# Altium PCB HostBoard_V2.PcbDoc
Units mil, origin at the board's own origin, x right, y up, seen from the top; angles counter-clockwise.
Board outline 3920 x 3930 mil, 2 copper layers (Top Layer, Bottom Layer); 20 components, 27 nets, 144 pads, 88 vias.
Unrouted connection lines stored in the file: 1.
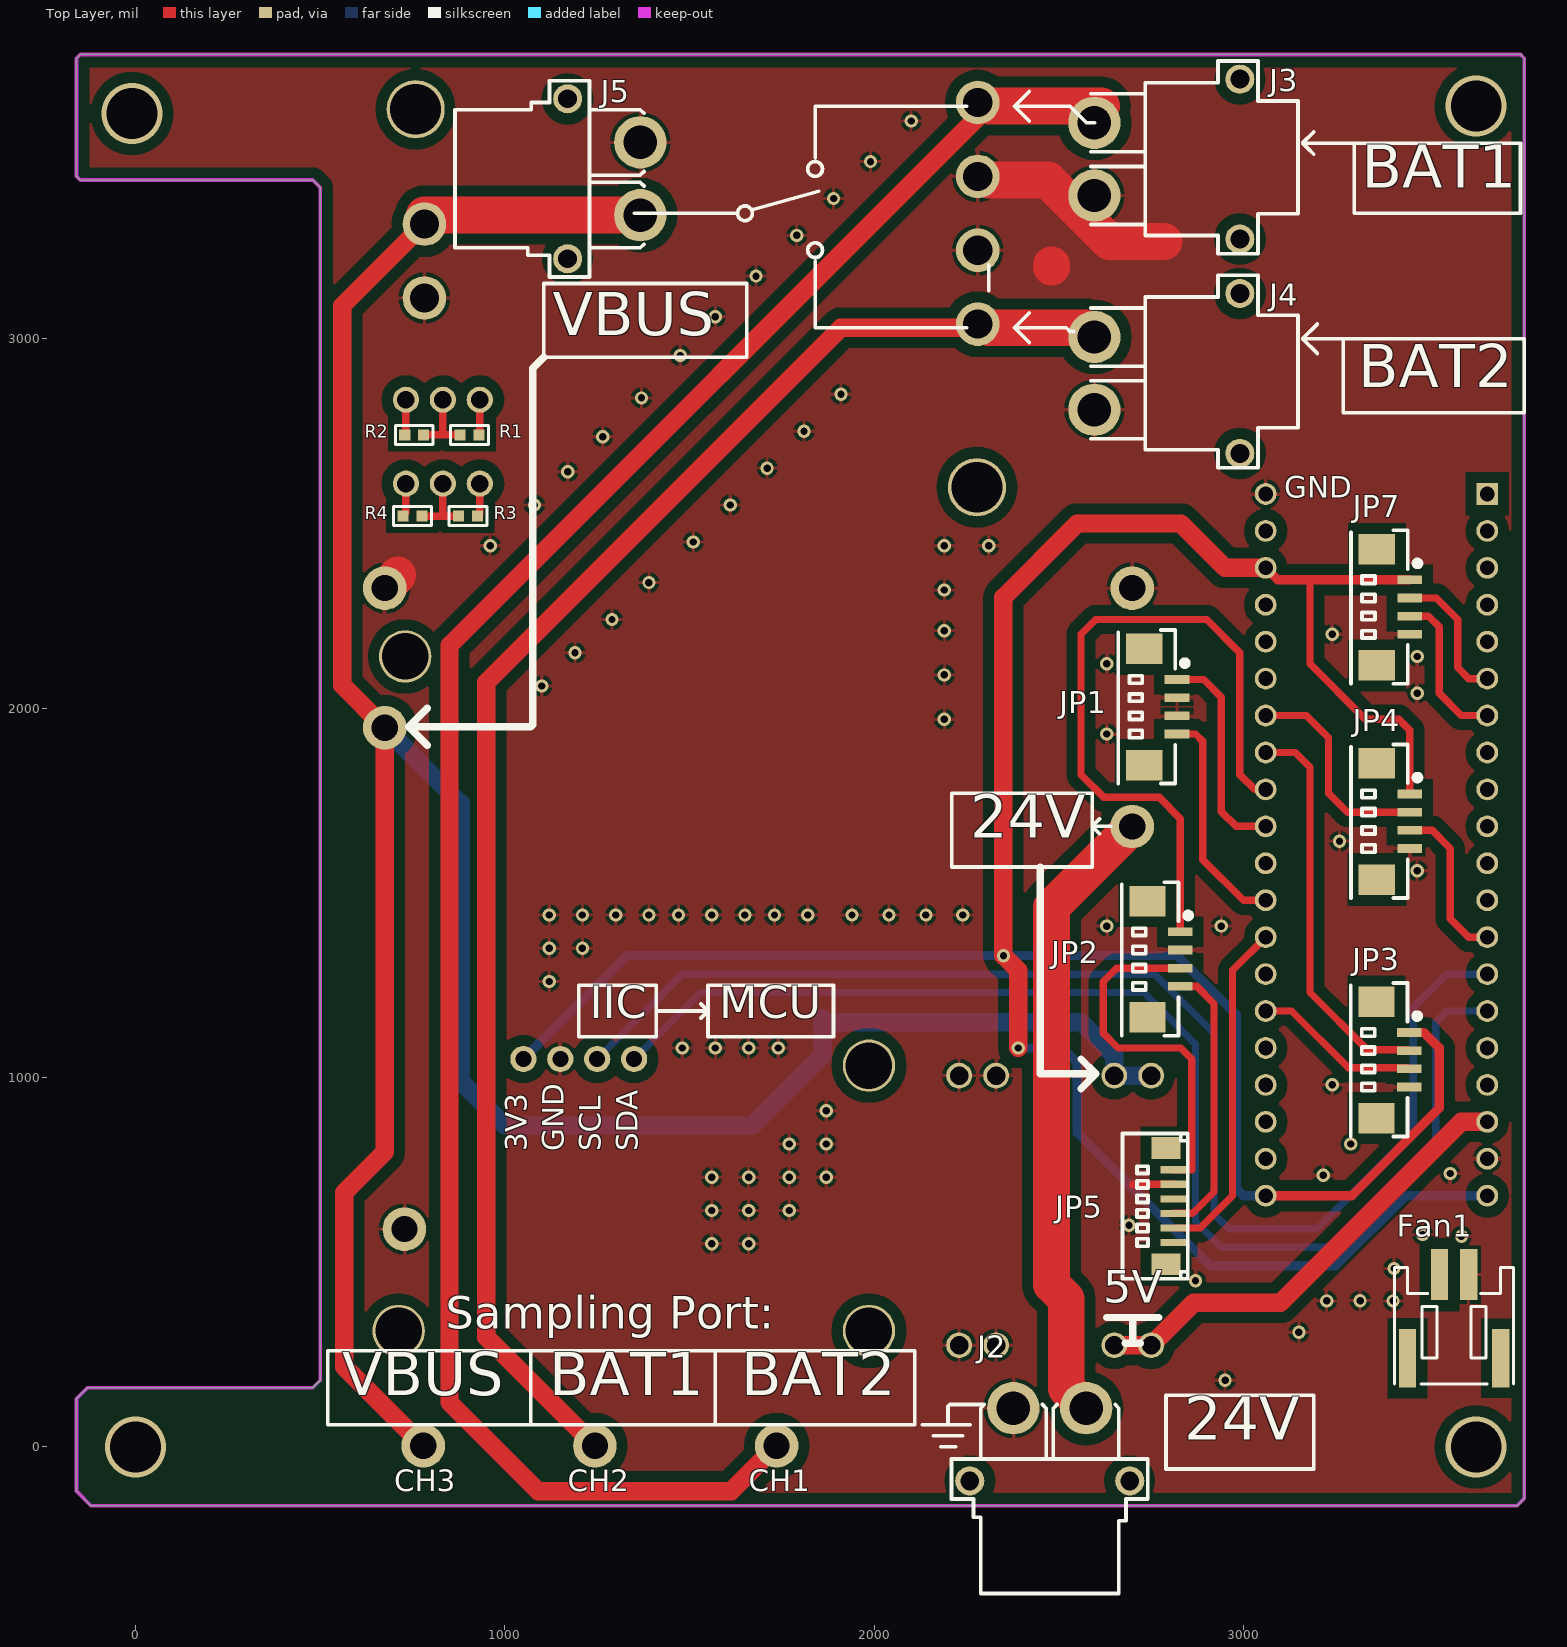
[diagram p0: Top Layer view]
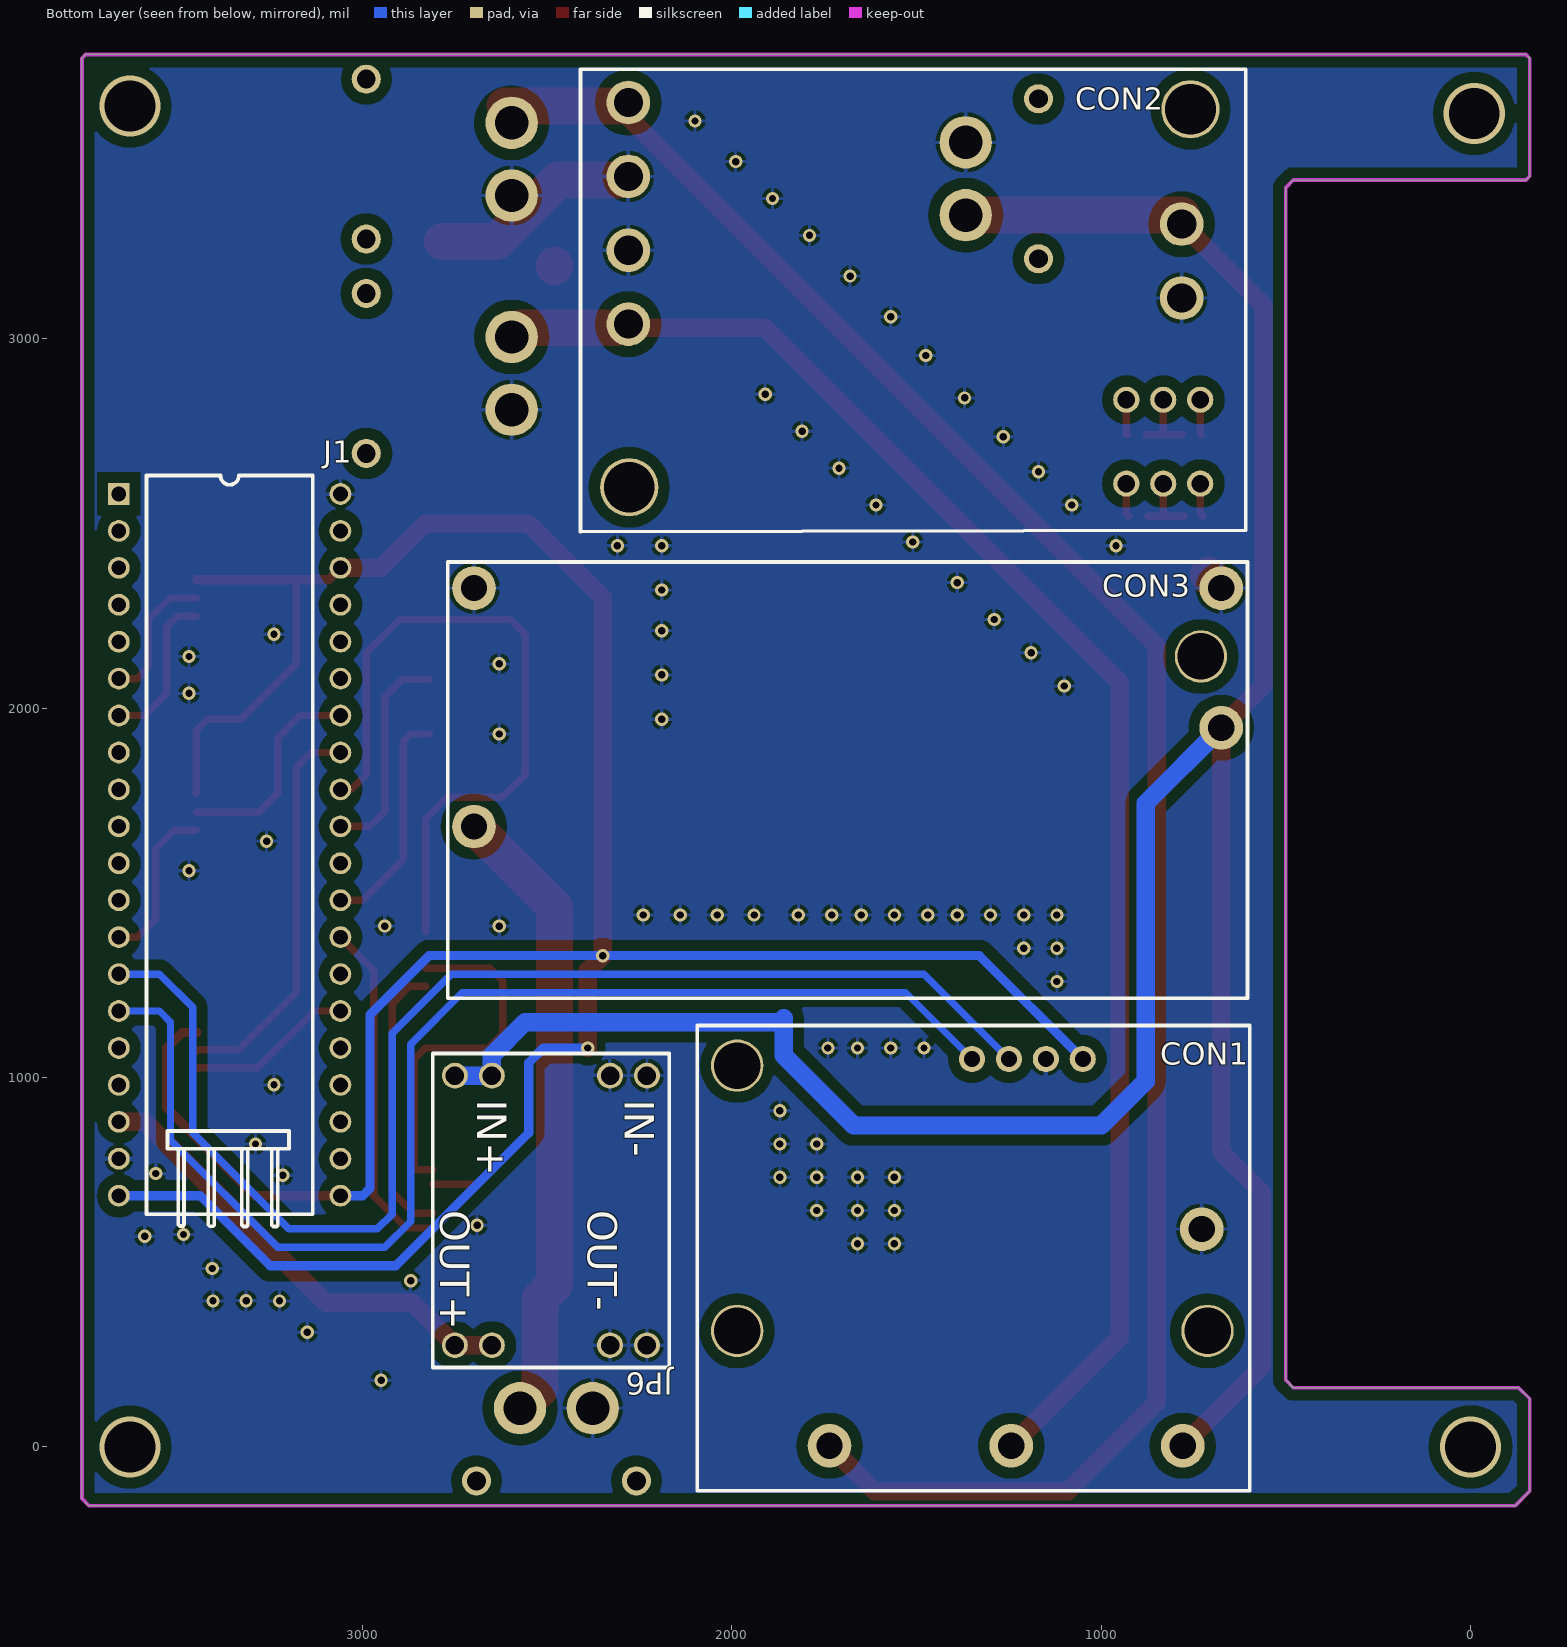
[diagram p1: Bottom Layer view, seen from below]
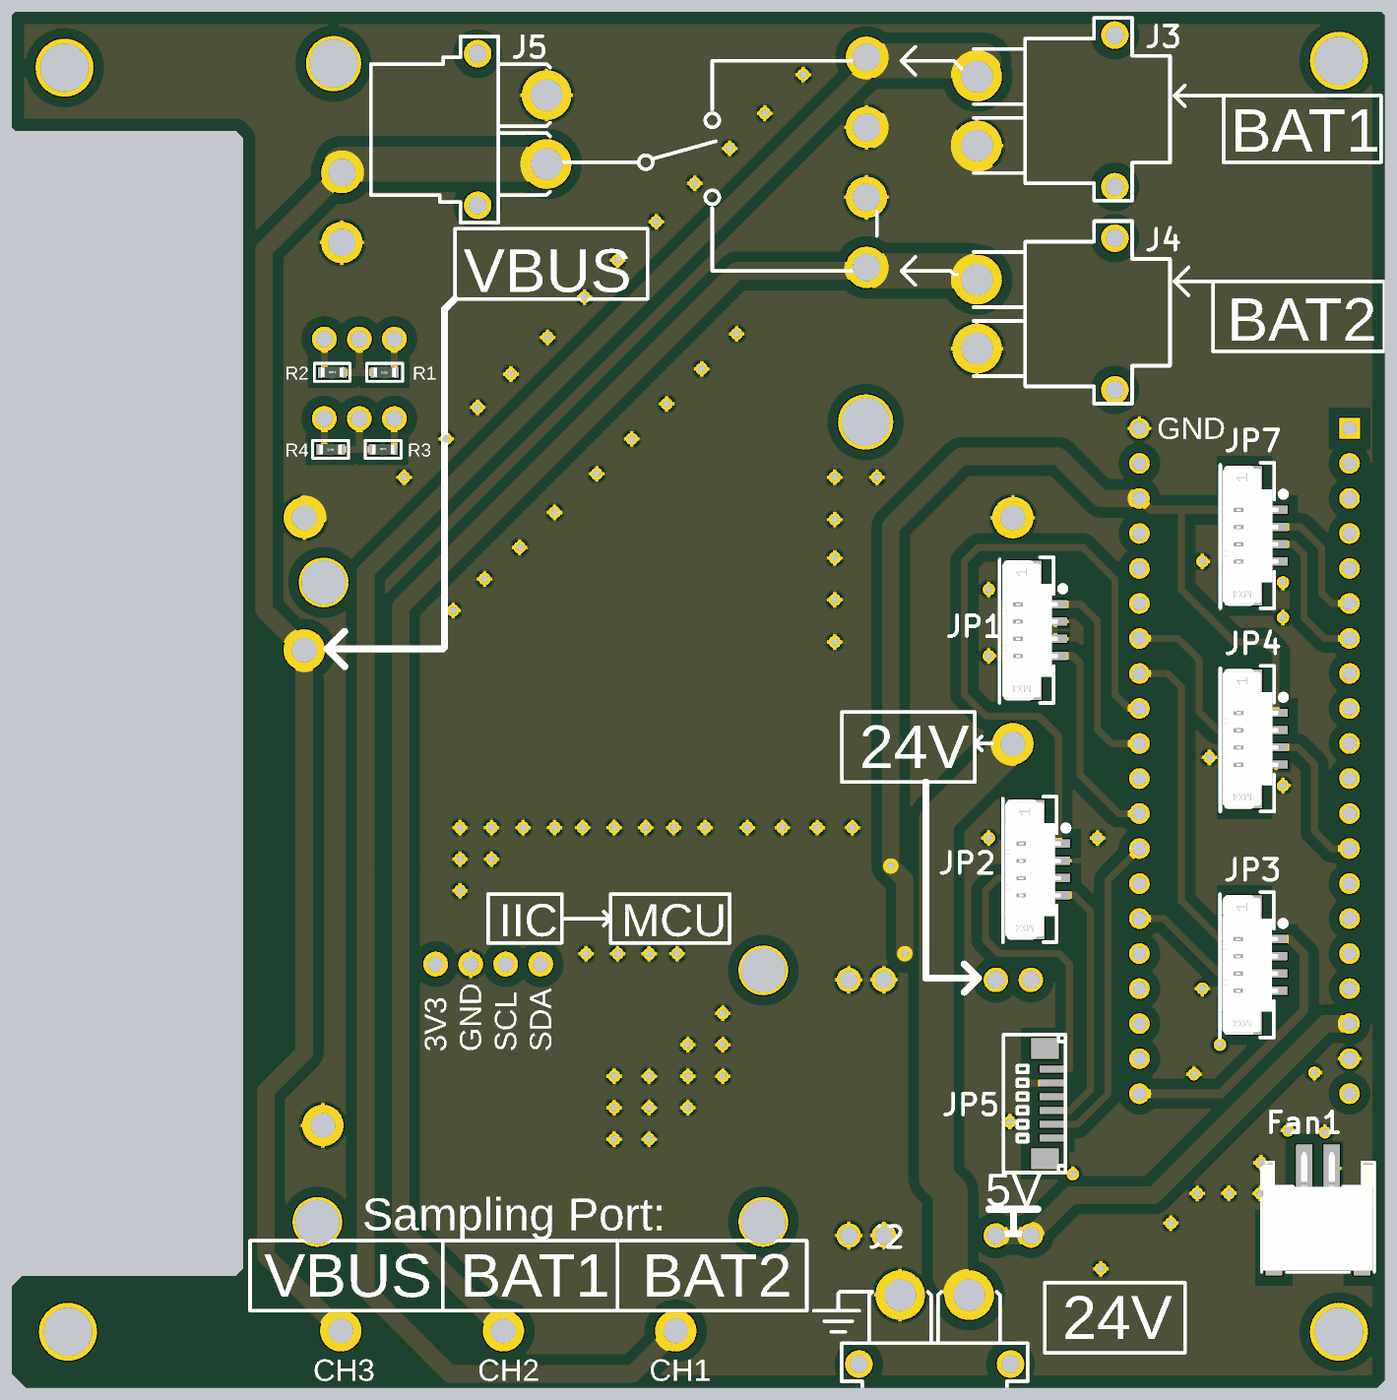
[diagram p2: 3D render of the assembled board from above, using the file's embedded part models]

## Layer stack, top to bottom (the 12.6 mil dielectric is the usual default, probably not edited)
Top Solder: solder mask 0.4, Solder Resist, Dk 3.5
Top Layer: signal copper 1.4
Dielectric 1: dielectric 12.6, FR-4, Dk 4.8
Bottom Layer: signal copper 1.4
Bottom Solder: solder mask 0.4, Solder Resist, Dk 3.5

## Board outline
-160,-120 -160,130 -130,160 480,160 500,180 500,3410 480,3430 -150,3430 -160,3440 -160,3760 -150,3770 3750,3770 3760,3760 3760,-140 3740,-160 -120,-160

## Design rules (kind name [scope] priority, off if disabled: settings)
Clearance [All] p1: gap=10 ignorepadtopadclearanceinfootprint=FALSE except(0: Arc-Hole Track-Hole SMDPad-Hole THPad-Hole Via-Hole Fill-Hole Poly-Hole Region-Hole Text-Hole; 30: Arc-Fill Arc-Poly Arc-Region Track-Fill Track-Poly Track-Region SMDPad-Fill SMDPad-Poly SMDPad-Region THPad-Fill THPad-Poly THPad-Region Via-Fill Via-Poly Via-Region Fill-Fill Fill-Poly Fill-Region Poly-Poly Poly-Region Region-Region)
PolygonConnect [All] p1: connectstyle=Relief reliefconductorwidth=10 reliefentries=4 polygonreliefangle="90 Angle" airgapwidth=10
RoutingVias [All] p1: holewidth=28 width=50 viastyle="Through Hole" minholewidth=28 minwidth=50 maxholewidth=28 maxwidth=50
SolderMaskExpansion [All] p1: expansion=4
Width [All] p1: maxlimit=196.85 minlimit=10 preferedwidth=39.37 minimp=50.000000 maximp=50.000000 favimp=50.000000
30 further rules are at their usual default settings.

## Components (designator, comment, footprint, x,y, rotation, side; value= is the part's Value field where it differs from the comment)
CON1 "Stereye-INA3221" STEREYE-INA3221 2094.09,-119.29 r90 bottom
CON2 "Stereye-PowerPath" STEREYE-POWERPATH 2410,3730 r180 bottom
CON3 "Stereye-BOOST" STEREYE-BOOST 1686.69,2002.2 r0 bottom
Fan1 "HDR-1X2" PH2.0-WS-2P 3570,240 r0 top
J1 "C8T6" C8T6 3360,1630 r180 bottom
J2 "CON2" "XT30 - F" 2475.29,104.71 r180 top
J3 "CON2" "XT30 - M" 2596.3,3486.54 r270 top
J4 "CON2" "XT30 - M" 2596.3,2906.54 r270 top
J5 "CON2" "XT30 - F" 1366.85,3433.46 r90 top
JP1 "KEY1" "MX 1.25-LS-4P" 2731,2003.28 r270 top
JP2 "KEY2" "MX 1.25-LS-4P" 2740,1320 r270 top
JP3 "HDR-1X4" "MX 1.25-LS-4P" 3360,1047.48 r270 top
JP4 "HDR-1X4" "MX 1.25-LS-4P" 3361,1693.28 r270 top
JP5 "HDR-1X6" SH1.0 2810,750 r270 top
JP6 "Stereye buck module" "STEREYE BUCK MODULE" 2490,640 r270 bottom
JP7 "HDR-1X4" "MX 1.25-LS-4P" 3361,2273.28 r270 top
R1 "68K" "R 0603_L" 904.41,2740 r180 top
R2 "30K" "R 0603_L" 754.41,2740 r0 top
R3 "68K" "R 0603_L" 900,2520 r0 top
R4 "36K" "R 0603_L" 750,2520 r180 top

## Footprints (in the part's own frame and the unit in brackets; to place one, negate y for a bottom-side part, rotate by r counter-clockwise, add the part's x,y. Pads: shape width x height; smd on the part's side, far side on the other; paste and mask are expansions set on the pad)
C8T6 [mm]
  rect 1.5x1.5 hole 1.016: 1(-7.62,24.13)
  round 1.5 hole 1.016: 2(-7.62,21.59) 3(-7.62,19.05) 4(-7.62,16.51) 5(-7.62,13.97) 6(-7.62,11.43) 7(-7.62,8.89) 8(-7.62,6.35) 9(-7.62,3.81) 10(-7.62,1.27) 11(-7.62,-1.27) 12(-7.62,-3.81) 13(-7.62,-6.35) 14(-7.62,-8.89) 15(-7.62,-11.43) 16(-7.62,-13.97) 17(-7.62,-16.51) 18(-7.62,-19.05) 19(-7.62,-21.59) 20(-7.62,-24.13) 21(7.62,-24.13) 22(7.62,-21.59) 23(7.62,-19.05) 24(7.62,-16.51) 25(7.62,-13.97) 26(7.62,-11.43) 27(7.62,-8.89) 28(7.62,-6.35) 29(7.62,-3.81) 30(7.62,-1.27) 31(7.62,1.27) 32(7.62,3.81) 33(7.62,6.35) 34(7.62,8.89) 35(7.62,11.43) 36(7.62,13.97) 37(7.62,16.51) 38(7.62,19.05) 39(7.62,21.59) 40(7.62,24.13)
  silkscreen extent -5.72,-26.25 5.72,25.4
"MX 1.25-LS-4P" [mm] "长：9.75m，宽：3.7mm，高：4.7mm"
  rect 2.1x2.5 smd: 0(-4,0) 0(4,0)
  rect 0.6x1.7 smd: 1(-1.889,2.261) 2(-0.639,2.261) 3(0.611,2.261) 4(1.861,2.261)
  silkscreen extent -5.29,-1.78 5.27,2.99, body extent -5.07,-1.6 5.07,2.5, height 4.7
PH2.0-WS-2P [mm] "长：8mm，宽：7.6mm，高：5.5mm"
  rect 1.2x4 smd: 0(-3.2,-0.006) 0(3.2,-0.006)
  rect 1.2x3.5 smd: 1(-1,5.744) 2(1,5.744)
  silkscreen extent -4.1,-1.78 4.1,6.22, body extent -4,-1.65 4,6.95, height 5.55
"R 0603_L" [mil] "1/10W贴片电阻                 淘宝ID:黄晶宝石"
  rect 30x30 smd: 1(-25.59,0) 2(25.59,0)
  silkscreen extent -51,-26 51,26, body extent -31,-16 32,16, height 16
SH1.0 [mm]
  rect 1.5x2 smd: 0(-1.5,-0.5) 0(6.5,-0.5)
  rect 0.5x1.8 smd: 1(0,0) 2(1,0) 3(2,0) 4(3,0) 5(4,0) 6(5,0)
  silkscreen extent -2.5,-3.5 7.5,1
"STEREYE BUCK MODULE" [mil]
  round 70 hole 50: 1(-365,260) 2(-365,160) 3(-365,-160) 4(-365,-260) 5(365,-260) 6(365,-160) 7(365,160) 8(365,260)
  silkscreen extent -425,-320 425,320
STEREYE-BOOST [mm]
  round 3.6 hole 3.2: 0(-24.3,-3.5)
  round 3 hole 1.8: 1(-25.7,1.4) 2(-25.7,-8.2) 3(25.7,-8.2) 4(25.7,8.2)
  silkscreen extent -27.5,-10 27.5,20
STEREYE-INA3221 [mm]
  round 3.6 hole 3.2: 0(11,-35.1) 0(11,-2.75) 0(29.25,-2.75)
  round 3 hole 1.8: 1(3.1,-9.1) 2(3.1,-21.6) 3(3.1,-33.4) 4(18,-34.7)
  round 1.8 hole 1.1: 5(29.7,-26.52) 6(29.7,-23.98) 7(29.7,-21.44) 8(29.7,-18.9)
  silkscreen extent 0,-38 32,0
STEREYE-POWERPATH [mm]
  round 4 hole 3.5: 0(3.35,-28.75) 0(41.95,-2.75)
  round 3 hole 2: 1(3.29,-2.29) 2(3.29,-7.37) 3(3.29,-12.45) 4(3.29,-17.53) 5(41.35,-15.73) 6(41.35,-10.65)
  round 1.8 hole 1.2: 7(37.54,-22.73) 8(40.08,-22.73) 9(42.62,-22.73) 10(37.54,-28.5) 11(40.08,-28.5) 12(42.62,-28.5)
  silkscreen extent 0,-31.8 45.75,0
"XT30 - F" [mm]
  round 2 hole 1.3: 0(-5.5,5) 0(5.5,5)
  round 3.6 hole 2.3: 1(-2.5,0) 2(2.5,0)
  silkscreen extent -6.75,-0.25 6.75,12.75
"XT30 - M" [mm]
  round 2 hole 1.3: 0(-5.5,10) 0(5.5,10)
  round 3.6 hole 2.3: 1(-2.5,0) 2(2.5,0)
  silkscreen extent -6.75,-0.25 6.5,14

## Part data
Fan1: library part "Header 2", "2P接插件"
J1: "C8T6转接"
JP1 JP2 JP3 JP4 JP7: library part "Header 4", "4P接插件"
JP5: library part "Header 6", "6P接插件"
R1 R2 R3 R4: library part R, "贴片电阻"

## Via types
v1: diameter 36, hole 20, Top Layer to Bottom Layer, 84 vias
v2: diameter 165.35, hole 137.8, Top Layer to Bottom Layer, 4 vias

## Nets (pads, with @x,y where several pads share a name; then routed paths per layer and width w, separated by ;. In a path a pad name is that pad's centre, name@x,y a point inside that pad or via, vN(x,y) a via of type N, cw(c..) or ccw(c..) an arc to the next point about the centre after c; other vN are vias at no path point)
3V3: CON1.5 J1.20 J1.21 J1.38 JP3.1 JP4.1 JP7.1 | length 8421.4
  Top Layer w20: 3180,2347.64 3180,2120 3330,1970 3420,1970 3450,1940 JP4.1
  Top Layer w25: J1.21 3292.82,680 3530,917.18 3530,1080 3488.16,1121.84 JP3.1 ; J1.38 3092.36,2347.64 3180,2347.64 JP7.1
  Top Layer w50: v1(2390,1080) 2390,1290 v1(2350,1330) 2350,2300 2550,2500 2830,2500 2950,2380 J1.38
  Bottom Layer w25: CON1.5 1330,1330 v1(2350,1330) 2820,1330 2980,1170 2980,700 3000,680 J1.21 ; v1@2400,1080 2510,1080 2550,1040 2550,850 2910,490 3250,490 3440,680 J1.20
24V: CON3.4 J2.1 | length 1704
  Top Layer w100: J2.1 2520,158.43 2520,400 2480,440 2480,1460.87 CON3.4
+5: Fan1.1 J1.18 JP6.5 JP6.6 | length 1260.6
  Top Layer w50: JP6.6 JP6.5 2865,390 3100,390 3590,880 J1.18
GND: CON1.4 CON1.6 CON2.2 CON2.3 CON2.5 CON3.2 CON3.3 Fan1.2 J1.19 J1.40 J2.2 J3.2 J4.2 J5.2 JP1.2 JP1.3 JP2.2 JP3.4 JP4.4 JP5.2 JP6.1 JP6.2 JP6.7 JP6.8 JP7.4 | length 709
  Top Layer w20: 2700,710 2700.63,710.63 JP5.2
  Top Layer w100: CON3.2 CON3.2@710,2360.16 ; CON2.2@2310,3430 2470,3430 2636.85,3263.15 2785,3263.15 ; 2480,3195 2480,3200
  other v1: 2950,180 3150,310 3225,395 3405,395 3315.54,395.88 2870,450 3407.31,482.72 1560,550 1660,550 3590,570 3485,575 2690,600 1560,640 1660,640 1770,640 1560,730 1660,730 1770,730 1870,730 3215.88,735.54 3560,740 1770,820 1870,820 3290,820 1870,910 3240,980 1480,1080 1570,1080 1660,1080 1740,1080 1120,1260 1120,1350 1210,1350 2630,1410 2940,1410 1120,1440 1210,1440 1300,1440 1390,1440 1470,1440 1560,1440 1650,1440 1730,1440 1820,1440 1940,1440 2040,1440 2140,1440 2240,1440 3470,1560 3260,1640 2630,1930 2190,1970 3470,2040 1100,2060 2190,2090 2630,2120 3470,2140 1190,2150 3240,2200 2190,2210 1290,2240 2190,2320 1390,2340 960,2440 2190,2440 2310,2440 1510,2450 1080,2550 1610,2550 1170,2640 1710,2650 1265,2735 1810,2750 1370,2840 1910,2850 1475,2955 1570,3060 1680,3170 1790,3280 1890,3380 1990,3480 2100,3590
KEY1: J1.29 JP1.4 | length 613.8
  Top Layer w20: JP1.4 2870,1930 2890,1910 2890,1590 3000,1480 J1.29
KEY2: JP2.4 JP5.4 | length 754.4
  Top Layer w20: JP5.4 2861.89,631.89 2920,690 2920,1200 2873.28,1246.72 JP2.4
KEY2_GND: JP2.3 JP5.1 | length 982.9
  Top Layer w20: JP5.1 2860,750 2860,1050 2830,1080 2660,1080 2620,1120 2620,1260 2655.94,1295.94 JP2.3
KEYLED1+: J1.31 JP1.1 | length 586.3
  Top Layer w20: JP1.1 2892.36,2077.64 2940,2030 2940,1720 2980,1680 J1.31
KEYLED2+: J1.32 JP2.1 | length 1905.3
  Top Layer w20: JP2.1 2829,1701 2771.57,1758.43 2621.57,1758.43 2560,1820 2560,2200 2600,2240 2900,2240 2990,2150 2990,1820 3030,1780 J1.32
LED1G: J1.26 JP3.3 | length 453.9
  Top Layer w20: J1.26 3130,1180 3284.06,1025.94 3446.48,1025.94 JP3.3
LED1R: J1.33 JP3.2 | length 1080.8
  Top Layer w20: J1.33 3140,1880 3180,1840 3180,1230 3334.85,1075.15 3446.48,1075.15 JP3.2
LED2G: J1.13 JP4.3 | length 441.1
  Top Layer w20: JP4.3 3510.79,1669.21 3560,1620 3560,1430 3610,1380 J1.13
LED2R: J1.34 JP4.2 | length 586.2
  Top Layer w20: J1.34 3170,1980 3230,1920 3230,1770 3281.57,1718.43 JP4.2
NetCON2_7: CON2.7 R1.1 | length 96
  Top Layer w20: R1.1 932.05,2742.05 CON2.7
NetCON2_8: CON2.8 R1.2 R2.2 | length 195
  Top Layer w20: R2.2 829.41,2740 ; CON2.8 832.05,2742.64 829.41,2740 ; R1.2 829.41,2740
NetCON2_9: CON2.9 R2.1 | length 96.5
  Top Layer w20: R2.1 732.05,2743.23 CON2.9
NetCON2_10: CON2.10 R3.2 | length 90.6
  Top Layer w20: R3.2 932.05,2526.46 CON2.10
NetCON2_11: CON2.11 R3.1 R4.1 | length 187.6
  Top Layer w20: R4.1 830,2520 ; CON2.11 832.05,2522.04 830,2520 ; R3.1 830,2520
NetCON2_12: CON2.12 R4.2 | length 91.1
  Top Layer w20: R4.2 732.05,2527.64 CON2.12
RX: J1.7 JP7.3 | length 427
  Top Layer w20: JP7.3 3500.79,2249.21 3530,2220 3530,2040 3590,1980 J1.7
SCL: CON1.7 J1.14 | length 3563.1
  Bottom Layer w20: CON1.7 1480,1280 2760,1280 2920,1120 2920,630 2960,590 3200,590 3460,850 3460,1190 3550,1280 J1.14
SDA: CON1.8 J1.15 | length 3404.1
  Bottom Layer w20: CON1.8 1530,1230 2730,1230 2870,1090 2870,610 2940,540 3230,540 3520,830 3520,1150 3550,1180 J1.15
TX: J1.6 JP7.2 | length 376.6
  Top Layer w20: JP7.2 3521.57,2298.43 3580,2240 3580,2110 3610,2080 J1.6
V1: CON1.1 CON2.1 J3.1 | length 5455.8
  Top Layer w50: CON1.1 1613.07,-120 1090,-120 850,120 850,2170 CON2.1@2310,3630
  Top Layer w100: CON2.1@2310,3630 J3.1@2615,3630
V2: CON1.2 CON2.4 J4.1 | length 4243.2
  Top Layer w50: CON1.2 950,296.46 950,2070 1910,3030 CON2.4@2310,3030
  Top Layer w100: CON2.4@2310,3030 2571.26,3030 J4.1
VBUS: CON1.3 CON2.6 CON3.1 J5.1 JP6.3 JP6.4 | length 7450.3
  Top Layer w50: CON3.1@687.8,1960 CON3.1 ; CON2.6@770,3320 770,3300 560,3090 560,2061.97 CON3.1 ; CON1.3 565,216.89 565,688.33 674.88,798.21 CON3.1
  Top Layer w100: CON2.6 782.05,3335.04 J5.1
  Bottom Layer w50: CON3.1 880,1741.97 880,990 1000,870 1670,870 1860,1060 1860,1160 1870,1150 2560,1150 2650,1060 JP6.3 JP6.4
WAKE_UP: J1.28 JP5.5 | length 933.5
  Top Layer w20: JP5.5 2882.52,592.52 2970,680 2970,1290 J1.28
pads on no net: CON1.0 CON2.0 CON3.0 Fan1.0 J1.1 J1.2 J1.3 J1.4 J1.5 J1.8 J1.9 J1.10 J1.11 J1.12 J1.16 J1.17 J1.22 J1.23 J1.24 J1.25 J1.27 J1.30 J1.35 J1.36 J1.37 J1.39 J2.0 J3.0 J4.0 J5.0 JP1.0 JP2.0 JP3.0 JP4.0 JP5.0 JP5.3 JP5.6 JP7.0
copper on no net:
  other v2: 0,0 3630,0 -10,3610 3630,3630

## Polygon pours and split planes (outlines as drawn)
GND on Bottom Layer "GND_L02_P002" (solid, remove dead copper, pour order 2): -280,3770 -280,-290 3950,-290 3950,3760 3930,3780
GND on Top Layer "GND_L01_P000" (solid, remove dead copper, pour order 0): -200,3810 -200,-230 3870,-230 3870,3830

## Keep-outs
Keep-Out Layer:
  lines w10: -160,-120 -120,-160 3620,-160 3740,-160 3760,-140 3760,3760 3750,3770 500,3770 -150,3770 -160,3760 -160,3440 -150,3430 480,3430 500,3410 500,180 480,160 -130,160 -160,130 -160,-120

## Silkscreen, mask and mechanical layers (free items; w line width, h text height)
Top Overlay:
  circle w10: c1650,3340 r20
  circle w10: c1840,3240 r20
  circle w10: c1840,3460 r20
  lines w10: 1350,3340 1550,3340 1630,3340 ; 1410,1180 1550,1180 ; 1530,1160 1550,1180 ; 1670,3340 1670,3350 1850,3400 ; 1840,3210 1840,3140 1840,3030 2250,3030 ; 1840,3490 1840,3540 1840,3630 1970,3630 2250,3630 ; 2130,60 2200,60 ; 2160,30 2240,30 ; 2180,0 2220,0 ; 2260,60 2200,60 ; 2294.43,114.5 2204.5,114.5 2200,110 2200,60 ; 2310,3130 2310,3170 2310,3200 ; 2420,2990 2380,3030 ; 2420,3590 2380,3630 ; 2540,3020 2530,3020 2520,3030 2380,3030 ; 2596.3,3584.96 2575.04,3584.96 2530,3630 2380,3630 ; 2610,1660 2590,1680 ; 2640,1680 2590,1680 ; 3180,3510 3160,3530 ; 3190,3500 3160,3530 ; 3200,2960 3160,3000 ; 1070,60 1570,60 ; 1070,60 520,60 520,260 1070,260 ; 1070,60 1070,260 ; 1070,260 1570,260 ; 1550,1180 1530,1200 1550,1180 ; 1570,60 2110,60 2110,260 1570,260 ; 1570,60 1570,260 ; 2380,3030 2420,3070 2380,3030 ; 2380,3630 2420,3670 2380,3630 ; 2590,1680 2610,1700 2590,1680 ; 3160,3000 3200,3040 3160,3000 ; 3160,3000 3270,3000 ; 3160,3530 3190,3560 3160,3530 ; 3160,3530 3300,3530 ; 3270,3000 3760,3000 3760,2800 3270,2800 3270,3000 ; 3300,3530 3750,3530 3750,3340 3300,3340 3300,3530 ; 1105,2950 1655,2950 1655,3150 1105,3150 1105,2950 ; 1200,1110 1410,1110 1410,1250 1200,1250 1200,1110 ; 1550,1110 1890,1110 1890,1250 1550,1250 1550,1110 ; 2210,1570 2210,1770 2590,1770 2590,1570 2210,1570 ; 2790,-60 3190,-60 3190,140 2790,140 2790,-60
  lines w20: 790,1900 740,1950 ; 790,2000 740,1950 ; 1105,2950 1075,2920 1075,1955 1070,1950 740,1950 ; 2450,1570 2450,1010 2600,1010 ; 2560,970 2600,1010 ; 2630,350 2650,350 2770,350 ; 2680,280 2720,280 ; 2700,280 2700,340 ; 2600,1010 2560,1050 2600,1010
  text "BAT1" at 3320,3370 h200
  text "VBUS" at 1130,2970 h200
  text "BAT2" at 3310,2830 h200
  text "GND" at 3110,2550 h100
  text "24V" at 2260,1610 h200
  text "IIC" at 1230,1130 h150
  text "MCU" at 1580,1130 h150
  text "3V3" at 1080,800 h100 r90
  text "GND" at 1180,800 h100 r90
  text "SCL" at 1280,800 h100 r90
  text "SDA" at 1380,800 h100 r90
  text "5V" at 2620,360 h150
  text "Sampling Port:" at 840,290 h150
  text "VBUS" at 560,100 h200
  text "BAT1" at 1120,100 h200
  text "BAT2" at 1640,100 h200
  text "24V" at 2840,-20 h200
  text "CH3" at 700,-140 h100
  text "CH2" at 1170,-140 h100
  text "CH1" at 1660,-140 h100

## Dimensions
500,3770 to -120,-160 on Mechanical 15
-10,3610 to 0,0 on Mechanical 15
-10,3610 to -150,3770 on Mechanical 15
-10,3610 to -160,3760 on Mechanical 15
-160,-120 to 0,0 on Mechanical 15
-120,-160 to 0,0 on Mechanical 15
